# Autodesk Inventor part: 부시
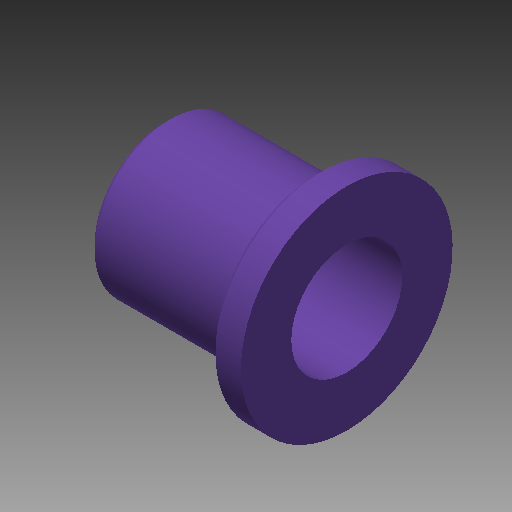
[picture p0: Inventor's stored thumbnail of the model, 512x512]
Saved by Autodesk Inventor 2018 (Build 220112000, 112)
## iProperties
Created: 2019-10
Part Number: 부시
Material: 강철, 연강
Document SubType Name: Modeling
Designer: mduedu
Density: 1 g/cm^3
Appearance: 보라색
Author: mduedu
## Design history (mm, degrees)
sketch "스케치1"
  geometry: L1 (0, 0)-(-18, 0); L2 (0, -5.5)-(0, -10.5); L3 (0, -10.5)-(-3, -10.5); L4 (-3, -10.5)-(-3, -7.5); L5 (-3, -7.5)-(-18, -7.5); L6 (-18, -7.5)-(-18, -5.5); L7 (-18, -5.5)-(0, -5.5)
  constraints: 14 end point, 3 parallel, 2 horizontal, 2 perpendicular, 2 vertical alignment
  dimensions: "d0" = 18 distance of L1.start L1.end; "d1" = 11 diameter of L7 L1; "d2" = 15 diameter of L5 L1; "d3" = 21 diameter of L3 L1; "d4" = 3 distance of L2.end L3.end
revolve "회전1" sketch "스케치1" stored, may be unused: angle "d5" = 90 deg
chamfer "모따기1" distance "d6" = 0.5; stored, may be unused: second distance "d7" = 2, angle "d8" = 45 deg
chamfer "모따기2" distance "d9" = 0.5; stored, may be unused: second distance "d10" = 2, angle "d11" = 45 deg
node "솔리드1"
